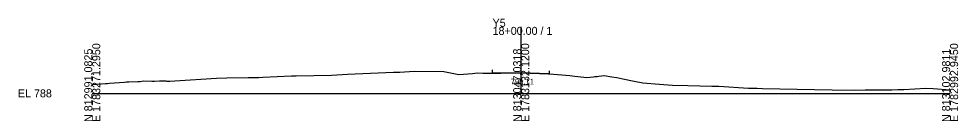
# Model space of a CAD drawing. Extents: x -26 to 1603, y -10 to 6526.
# Drawn here: x 1274.3 to 1602.8, y 4990.3 to 5026 of the extents above; entities that cross this region are included whole.
import ezdxf

# ---------------------------------------------------------------- set-up
doc = ezdxf.new("R2010")
doc.units = 0
for name, color, linetype in [('Exist Cross Section Cell', 7, 'Continuous'), ('Exist XS Center Line Elevation Label', 7, 'Continuous'), ('Exist XS Ground Line', 7, 'Continuous'), ('Prop XS EOT Tick Mark', 7, 'Continuous'), ('Prop XS Finish Grade Pavement', 7, 'Continuous')]:
    doc.layers.add(name, color=color, linetype=linetype)

msp = doc.modelspace()

# ---------------------------------------------------------------- linework, layer by layer
at = {"layer": 'Exist Cross Section Cell'}
for p, q in [((1450, 5000), (1450, 5023.2)), ((1300, 5000), (1450, 5000)), ((1450, 5000), (1600, 5000))]:
    msp.add_line(p, q, dxfattribs=at)
at = {"layer": 'Exist XS Ground Line'}
for p, q in [((1389.24, 5006.68), (1405.3, 5007.38)), ((1405.3, 5007.38), (1407.57, 5007.43)), ((1407.57, 5007.43), (1412.62, 5007.73)), ((1412.62, 5007.73), (1422.9, 5007.58)), ((1422.9, 5007.58), (1428.23, 5006.55)), ((1428.23, 5006.55), (1432.95, 5006.96)), ((1432.95, 5006.96), (1433.79, 5007.07)), ((1433.79, 5007.07), (1434.68, 5007.12)), ((1434.68, 5007.12), (1436.63, 5007.06)), ((1436.63, 5007.06), (1439.94, 5007.05)), ((1439.94, 5007.05), (1442.9, 5007.07)), ((1442.9, 5007.07), (1449.95, 5007.11)), ((1449.95, 5007.11), (1459.58, 5006.77)), ((1306, 5003.51), (1311.26, 5003.94)), ((1311.26, 5003.94), (1312.01, 5003.97)), ((1312.01, 5003.97), (1312.81, 5004.01)), ((1312.81, 5004.01), (1315.96, 5004.14)), ((1315.96, 5004.14), (1316.81, 5004.19)), ((1316.81, 5004.19), (1317.94, 5004.32)), ((1317.94, 5004.32), (1320.88, 5004.23)), ((1320.88, 5004.23), (1321.8, 5004.27)), ((1321.8, 5004.27), (1323.56, 5004.34)), ((1323.56, 5004.34), (1324.29, 5004.35)), ((1324.29, 5004.35), (1325.69, 5004.38)), ((1325.69, 5004.38), (1326.07, 5004.31)), ((1326.07, 5004.31), (1326.7, 5004.24)), ((1326.7, 5004.24), (1327.13, 5004.23)), ((1327.13, 5004.23), (1328.85, 5004.35)), ((1328.85, 5004.35), (1343.44, 5005.33)), ((1343.44, 5005.33), (1347.05, 5005.42)), ((1347.05, 5005.42), (1354.5, 5005.51)), ((1354.5, 5005.51), (1358.19, 5005.54)), ((1358.19, 5005.54), (1359.71, 5005.64)), ((1359.71, 5005.64), (1364.62, 5005.89)), ((1364.62, 5005.89), (1369.67, 5006.11)), ((1369.67, 5006.11), (1371.31, 5006.17)), ((1371.31, 5006.17), (1383.68, 5006.38)), ((1383.68, 5006.38), (1389.24, 5006.68)), ((1459.58, 5006.77), (1459.92, 5006.76)), ((1459.92, 5006.76), (1467.06, 5006.28)), ((1467.06, 5006.28), (1467.88, 5006.15)), ((1467.88, 5006.15), (1468.72, 5006.04)), ((1468.72, 5006.04), (1472.97, 5005.48)), ((1472.97, 5005.48), (1475.25, 5005.81)), ((1475.25, 5005.81), (1475.78, 5005.87)), ((1475.78, 5005.87), (1476.52, 5005.94)), ((1476.52, 5005.94), (1477.21, 5006.04)), ((1477.21, 5006.04), (1479.02, 5006.24)), ((1479.02, 5006.24), (1481.69, 5005.73)), ((1481.69, 5005.73), (1483.42, 5005.58)), ((1483.42, 5005.58), (1485.56, 5005.08)), ((1485.56, 5005.08), (1489.57, 5004.23)), ((1489.57, 5004.23), (1492.51, 5003.7)), ((1492.51, 5003.7), (1493.94, 5003.59)), ((1493.94, 5003.59), (1496.91, 5003.35)), ((1300, 5003.06), (1304.61, 5003.41)), ((1304.61, 5003.41), (1305.29, 5003.48)), ((1305.29, 5003.48), (1306, 5003.51)), ((1496.91, 5003.35), (1502.95, 5002.9)), ((1502.95, 5002.9), (1508.26, 5002.75)), ((1508.26, 5002.75), (1516.66, 5002.56)), ((1516.66, 5002.56), (1519.13, 5002.49)), ((1519.13, 5002.49), (1529.53, 5001.85)), ((1529.53, 5001.85), (1531.86, 5001.78)), ((1531.86, 5001.78), (1532.48, 5001.77)), ((1532.48, 5001.77), (1534.4, 5001.74)), ((1534.4, 5001.74), (1546.47, 5001.5)), ((1546.47, 5001.5), (1552.61, 5001.4)), ((1552.61, 5001.4), (1558.81, 5001.22)), ((1558.81, 5001.22), (1566.7, 5001.16)), ((1566.7, 5001.16), (1570.29, 5001.18)), ((1570.29, 5001.18), (1573.34, 5001.24)), ((1573.34, 5001.24), (1579.67, 5001.28)), ((1579.67, 5001.28), (1581.75, 5001.3)), ((1581.75, 5001.3), (1583.88, 5001.4)), ((1583.88, 5001.4), (1591.5, 5001.79)), ((1591.5, 5001.79), (1594.09, 5001.66)), ((1594.09, 5001.66), (1600, 5001.29))]:
    msp.add_line(p, q, dxfattribs=at)
at = {"layer": 'Prop XS EOT Tick Mark'}
for p, q in [((1439.94, 5007.18), (1439.94, 5008.18)), ((1459.92, 5006.89), (1459.92, 5007.89))]:
    msp.add_line(p, q, dxfattribs=at)
at = {"layer": 'Prop XS Finish Grade Pavement'}
for p, q in [((1439.94, 5007.18), (1442.9, 5007.19)), ((1442.9, 5007.19), (1449.95, 5007.24)), ((1449.95, 5007.24), (1459.58, 5006.9)), ((1459.58, 5006.9), (1459.92, 5006.89))]:
    msp.add_line(p, q, dxfattribs=at)

# ---------------------------------------------------------------- texts
at = {"layer": 'Exist Cross Section Cell'}
for s, p in [('Y5', (1440, 5023.2)), ('18+00.00 / 1', (1440, 5020.4)), ('EL 788', (1274, 4998.6))]:
    msp.add_text(s, height=2.8, dxfattribs=at).set_placement(p)
for s, p in [('E 1783271.2950', (1302.8, 4990)), ('E 1783132.1200', (1452.8, 4990)), ('E 1782992.9450', (1602.8, 4990)), ('N 812991.0825', (1300, 4990)), ('N 813047.0318', (1450, 4990)), ('N 813102.9811', (1600, 4990))]:
    msp.add_text(s, height=2.8, rotation=90, dxfattribs=at).set_placement(p)
at = {"layer": 'Exist XS Center Line Elevation Label'}
msp.add_text('795.11', height=2, dxfattribs=at).set_placement((1446.32, 5003.11))

doc.saveas('drawing.dxf')
